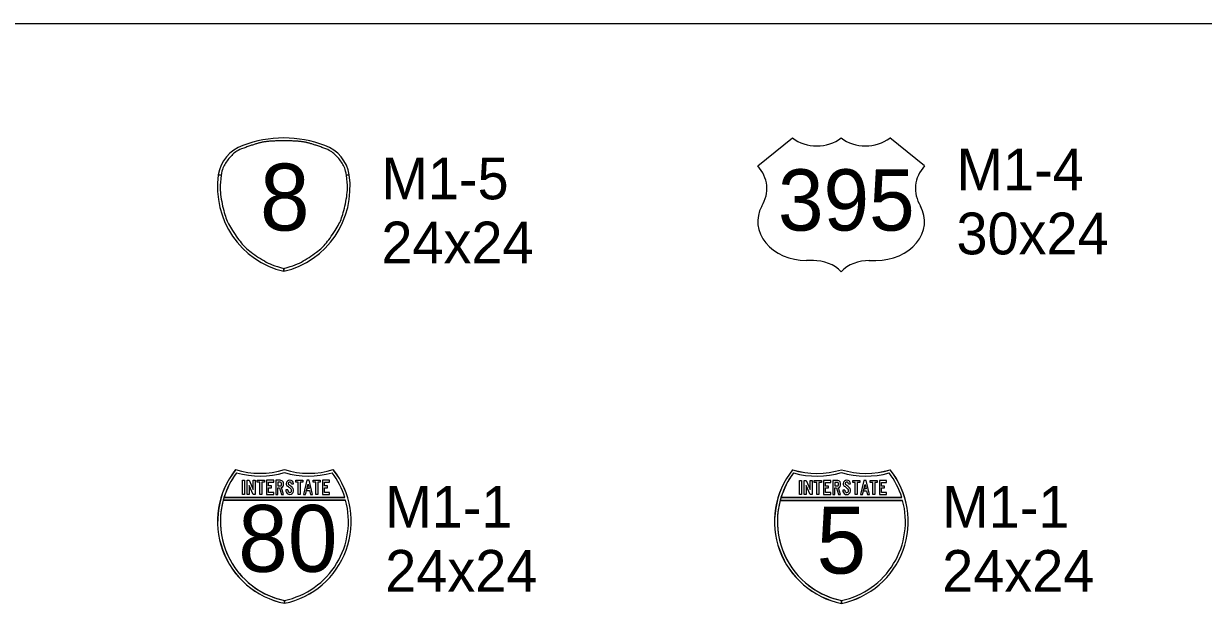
# Model space of a CAD drawing. Extents: x 1458 to 4498, y 17709 to 24109.
# Drawn here: x 1882 to 2305.5, y 20459 to 20667.1 of the extents above; entities that cross this region are included whole.
import ezdxf

# ---------------------------------------------------------------- set-up
doc = ezdxf.new("R2010")
doc.units = 0
doc.layers.add('P_ODOT_PLAN_TBlock', color=7, linetype='Continuous')
doc.layers.add('P_TRAF_TCP_General', color=7, linetype='Continuous')

msp = doc.modelspace()

# ---------------------------------------------------------------- linework, layer by layer
at = {"layer": 'P_ODOT_PLAN_TBlock'}
msp.add_line((1458.44, 20667.08), (3378.44, 20667.08), dxfattribs=at)
at = {"layer": 'P_TRAF_TCP_General'}
for p, q in [((2145.54, 20616.04), (2158.02, 20626.04)), ((2205.46, 20616.04), (2192.97, 20626.04)), ((1952.92, 20612.63), (1951.89, 20612.77)), ((1951.89, 20612.77), (1952.92, 20612.63)), ((1998.91, 20612.77), (1997.88, 20612.63)), ((1997.88, 20612.63), (1998.91, 20612.77)), ((2165.51, 20582.06), (2163.01, 20582.06)), ((2185.48, 20582.06), (2187.98, 20582.06)), ((1975.39, 20579.24), (1975.4, 20578.18)), ((1975.4, 20578.18), (1975.39, 20579.24)), ((1975.34, 20498.13), (1974.62, 20500.55)), ((1978.18, 20501.96), (1978.88, 20501.96)), ((2175.31, 20498.1), (2174.58, 20500.52)), ((2178.14, 20501.93), (2178.84, 20501.93)), ((1997.6, 20496.01), (1953.65, 20496.01)), ((1953.65, 20496.01), (1997.6, 20496.01)), ((1953.65, 20496.01), (1997.6, 20496.01)), ((1953.94, 20497.01), (1997.31, 20497.01)), ((1997.31, 20497.01), (1953.94, 20497.01)), ((1997.31, 20497.01), (1953.94, 20497.01)), ((1997.31, 20497.01), (1953.94, 20497.01)), ((1976.82, 20499.71), (1976.11, 20499.71)), ((1997.6, 20496.01), (1997.6, 20496.01)), ((2197.56, 20495.98), (2153.61, 20495.98)), ((2153.61, 20495.98), (2197.56, 20495.98)), ((2153.61, 20495.98), (2197.56, 20495.98)), ((2153.9, 20496.98), (2197.27, 20496.98)), ((2197.27, 20496.98), (2153.9, 20496.98)), ((2197.27, 20496.98), (2153.9, 20496.98)), ((2197.27, 20496.98), (2153.9, 20496.98)), ((2176.78, 20499.68), (2176.07, 20499.68)), ((2197.56, 20495.98), (2197.56, 20495.98)), ((1975.62, 20460.05), (1975.62, 20459.03)), ((1975.62, 20459.03), (1975.62, 20460.05)), ((1975.62, 20460.05), (1975.62, 20459.03)), ((1975.62, 20459.03), (1975.62, 20460.05)), ((1975.62, 20459.04), (1975.62, 20459.03)), ((1975.62, 20459.03), (1975.62, 20459.04)), ((2175.58, 20459), (2175.58, 20460.02)), ((2175.58, 20459), (2175.58, 20460.02)), ((2175.58, 20459), (2175.58, 20459.02)), ((2175.59, 20460.02), (2175.59, 20459)), ((2175.59, 20460.02), (2175.59, 20459)), ((2175.59, 20459.02), (2175.59, 20459))]:
    msp.add_line(p, q, dxfattribs=at)
for points in [[(1975.39, 20579.24), (1975.4, 20579.24), (1975.41, 20579.24)], [(1974.09, 20503.17), (1972.55, 20503.17), (1972.55, 20498.13), (1973.25, 20498.13), (1973.25, 20500.46), (1973.9, 20500.46), (1974.61, 20498.13), (1975.34, 20498.13)], [(1974.09, 20502.46), (1973.25, 20502.46), (1973.25, 20501.17), (1974.11, 20501.17)], [(2174.05, 20503.14), (2172.51, 20503.14), (2172.51, 20498.1), (2173.21, 20498.1), (2173.21, 20500.44), (2173.87, 20500.44), (2174.57, 20498.1), (2175.31, 20498.1)], [(2174.05, 20502.44), (2173.21, 20502.44), (2173.21, 20501.14), (2174.08, 20501.14)]]:
    msp.add_lwpolyline(points, dxfattribs=at)
for points in [[(1960.62, 20503.17), (1961.33, 20503.17), (1961.33, 20498.13), (1960.62, 20498.13)], [(1963, 20503.17), (1964.39, 20499.92), (1964.39, 20503.17), (1965.1, 20503.17), (1965.1, 20498.13), (1964.39, 20498.13), (1963.01, 20501.37), (1963.01, 20498.13), (1962.3, 20498.13), (1962.3, 20503.17)], [(1966.8, 20502.46), (1965.87, 20502.46), (1965.87, 20503.17), (1968.44, 20503.17), (1968.44, 20502.46), (1967.51, 20502.46), (1967.51, 20498.13), (1966.8, 20498.13)], [(1969.91, 20498.84), (1969.91, 20500.45), (1971.02, 20500.45), (1971.02, 20501.15), (1969.91, 20501.15), (1969.91, 20502.46), (1971.78, 20502.46), (1971.78, 20503.17), (1969.21, 20503.17), (1969.21, 20498.13), (1971.78, 20498.13), (1971.78, 20498.84)], [(1980.61, 20502.46), (1979.68, 20502.46), (1979.68, 20503.17), (1982.25, 20503.17), (1982.25, 20502.46), (1981.32, 20502.46), (1981.32, 20498.13), (1980.61, 20498.13)], [(1983.72, 20500.19), (1983.55, 20499.48), (1984.65, 20499.48), (1984.97, 20498.13), (1985.7, 20498.13), (1984.48, 20503.17), (1983.72, 20503.17), (1982.5, 20498.13), (1983.23, 20498.13), (1984.1, 20501.73), (1984.48, 20500.19)], [(1986.88, 20502.46), (1985.95, 20502.46), (1985.95, 20503.17), (1988.52, 20503.17), (1988.52, 20502.46), (1987.59, 20502.46), (1987.59, 20498.13), (1986.88, 20498.13)], [(1989.99, 20498.84), (1989.99, 20500.45), (1991.1, 20500.45), (1991.1, 20501.15), (1989.99, 20501.15), (1989.99, 20502.46), (1991.86, 20502.46), (1991.86, 20503.17), (1989.29, 20503.17), (1989.29, 20498.13), (1991.86, 20498.13), (1991.86, 20498.84)], [(2160.58, 20503.14), (2161.29, 20503.14), (2161.29, 20498.1), (2160.58, 20498.1)], [(2162.96, 20503.14), (2164.35, 20499.9), (2164.35, 20503.14), (2165.06, 20503.14), (2165.06, 20498.1), (2164.35, 20498.1), (2162.97, 20501.34), (2162.97, 20498.1), (2162.26, 20498.1), (2162.26, 20503.14)], [(2166.76, 20502.44), (2165.83, 20502.44), (2165.83, 20503.14), (2168.4, 20503.14), (2168.4, 20502.44), (2167.47, 20502.44), (2167.47, 20498.1), (2166.76, 20498.1)], [(2169.87, 20498.81), (2169.87, 20500.42), (2170.98, 20500.42), (2170.98, 20501.13), (2169.87, 20501.13), (2169.87, 20502.44), (2171.74, 20502.44), (2171.74, 20503.14), (2169.17, 20503.14), (2169.17, 20498.1), (2171.74, 20498.1), (2171.74, 20498.81)], [(2180.58, 20502.44), (2179.64, 20502.44), (2179.64, 20503.14), (2182.21, 20503.14), (2182.21, 20502.44), (2181.28, 20502.44), (2181.28, 20498.1), (2180.58, 20498.1)], [(2183.69, 20500.16), (2183.51, 20499.45), (2184.61, 20499.45), (2184.93, 20498.1), (2185.66, 20498.1), (2184.44, 20503.14), (2183.68, 20503.14), (2182.46, 20498.1), (2183.19, 20498.1), (2184.06, 20501.71), (2184.44, 20500.16)], [(2186.84, 20502.44), (2185.91, 20502.44), (2185.91, 20503.14), (2188.48, 20503.14), (2188.48, 20502.44), (2187.55, 20502.44), (2187.55, 20498.1), (2186.84, 20498.1)], [(2189.96, 20498.81), (2189.96, 20500.42), (2191.06, 20500.42), (2191.06, 20501.13), (2189.96, 20501.13), (2189.96, 20502.44), (2191.82, 20502.44), (2191.82, 20503.14), (2189.25, 20503.14), (2189.25, 20498.1), (2191.82, 20498.1), (2191.82, 20498.81)]]:
    msp.add_lwpolyline(points, close=True, dxfattribs=at)
for centre, radius, start, end in [((1981.62, 20488.41), 29.99, 141.6689, 258.4631), ((1981.62, 20488.41), 29.99, 141.6689, 258.4631), ((1981.62, 20488.41), 29.99, 141.6689, 258.4631), ((1981.62, 20488.41), 29.99, 141.6689, 258.4631), ((1981.62, 20488.41), 29.97, 141.6894, 258.4569), ((1981.62, 20488.41), 28.99, 142.9958, 258.0595), ((1981.62, 20488.41), 28.99, 142.9958, 258.0595), ((1981.62, 20488.41), 28.99, 142.9957, 162.7366), ((1981.62, 20488.41), 28.99, 142.9958, 162.7366), ((1966.86, 20535.69), 29.99, 253.0091, 286.9909), ((1966.86, 20535.69), 29.99, 253.0091, 286.9909), ((1966.86, 20535.69), 29.99, 253.0091, 286.9909), ((1966.86, 20535.69), 29.99, 253.0091, 286.9909), ((1966.86, 20535.69), 30, 253.0296, 286.9817), ((1966.86, 20535.69), 30.99, 254.2925, 286.427), ((1966.86, 20535.69), 30.99, 254.2925, 286.427), ((1966.86, 20535.69), 30.99, 254.2925, 286.427), ((1966.86, 20535.69), 30.99, 254.2925, 286.427), ((1984.39, 20535.69), 29.99, 253.0091, 286.9909), ((1969.63, 20488.41), 29.99, 281.5369, 38.3311), ((1969.63, 20488.41), 29.99, 281.5385, 38.3311), ((1984.39, 20535.69), 29.99, 253.0091, 286.9909), ((1969.63, 20488.41), 29.99, 281.5385, 38.3311), ((1984.39, 20535.69), 29.99, 253.0091, 286.9909), ((1969.63, 20488.41), 29.99, 281.5385, 38.3311), ((1984.39, 20535.69), 29.99, 253.0091, 286.9909), ((1984.39, 20535.69), 30, 253.0183, 286.9704), ((1969.63, 20488.41), 29.97, 281.5446, 38.3106), ((1984.39, 20535.69), 30.99, 253.573, 285.7075), ((1984.39, 20535.69), 30.99, 253.573, 285.7075), ((1984.39, 20535.69), 30.99, 253.573, 285.7075), ((1984.39, 20535.69), 30.99, 253.573, 285.7075), ((1969.63, 20488.41), 28.99, 17.2633, 37.0042), ((1969.63, 20488.41), 28.99, 17.2633, 37.0042), ((1969.63, 20488.41), 28.99, 17.2633, 37.0042), ((1969.63, 20488.41), 28.99, 17.2633, 37.0042), ((2181.58, 20488.38), 29.99, 141.6689, 258.4631), ((2181.58, 20488.38), 29.99, 141.6689, 258.4631), ((2181.58, 20488.38), 29.99, 141.6689, 258.4631), ((2181.58, 20488.38), 29.99, 141.6689, 258.4631), ((2181.58, 20488.38), 29.97, 141.6894, 258.4569), ((2181.58, 20488.38), 28.99, 142.9958, 258.0595), ((2181.58, 20488.38), 28.99, 142.9958, 258.0595), ((2181.58, 20488.38), 28.99, 142.9957, 162.7366), ((2181.58, 20488.38), 28.99, 142.9958, 162.7366), ((2166.82, 20535.66), 29.99, 253.0091, 286.9909), ((2166.82, 20535.66), 29.99, 253.0091, 286.9909), ((2166.82, 20535.66), 29.99, 253.0091, 286.9909), ((2166.82, 20535.66), 29.99, 253.0091, 286.9909), ((2166.82, 20535.66), 30, 253.0296, 286.9817), ((2166.82, 20535.66), 30.99, 254.2925, 286.427), ((2166.82, 20535.66), 30.99, 254.2925, 286.427), ((2166.82, 20535.66), 30.99, 254.2925, 286.427), ((2166.82, 20535.66), 30.99, 254.2925, 286.427), ((2184.35, 20535.66), 29.99, 253.0091, 286.9909), ((2169.59, 20488.38), 29.99, 281.5369, 38.3311), ((2184.35, 20535.66), 29.99, 253.0091, 286.9909), ((2184.35, 20535.66), 29.99, 253.0091, 286.9909), ((2184.35, 20535.66), 29.99, 253.0091, 286.9909), ((2184.35, 20535.66), 30, 253.0183, 286.9704), ((2184.35, 20535.66), 30.99, 253.573, 285.7075), ((2184.35, 20535.66), 30.99, 253.573, 285.7075), ((2184.35, 20535.66), 30.99, 253.573, 285.7075), ((2184.35, 20535.66), 30.99, 253.573, 285.7075), ((2169.59, 20488.38), 29.99, 281.5385, 38.3311), ((2169.59, 20488.38), 29.99, 281.5385, 38.3311), ((2169.59, 20488.38), 29.99, 281.5385, 38.3311), ((2169.59, 20488.38), 29.97, 281.5446, 38.3106), ((2169.59, 20488.38), 28.99, 17.2633, 37.0042), ((2169.59, 20488.38), 28.99, 17.2633, 37.0042), ((2169.59, 20488.38), 28.99, 17.2633, 37.0042), ((2169.59, 20488.38), 28.99, 17.2633, 37.0042), ((1974.11, 20501.96), 1.21, 32.7773, 91.1677), ((1974.11, 20501.95), 0.519, 26.159, 91.9542), ((1974.15, 20501.62), 0.455, 265.1381, 343.1073), ((1973.33, 20501.8), 1.3, 346.1097, 16.6195), ((1974.12, 20501.64), 1.2, 294.5283, 328.7975), ((1973.66, 20501.81), 1.68, 332.0334, 28.7465), ((1977.58, 20501.93), 1.31, 1.3681, 176.3683), ((1977.44, 20501.97), 1.17, 177.9393, 233.9136), ((1974.32, 20496.53), 5.1, 45.9941, 61.57), ((1977.49, 20501.99), 0.507, 140.0639, 242.2325), ((1977.57, 20501.91), 0.615, 4.2694, 139.1342), ((1974.94, 20497.3), 4.83, 43.0003, 61.2981), ((1977.34, 20499.51), 0.872, 333.7597, 52.7126), ((1977.35, 20499.51), 1.56, 334.1366, 44.3106), ((2174.07, 20501.93), 1.21, 32.7773, 91.1677), ((2174.07, 20501.92), 0.519, 26.159, 91.9542), ((2174.11, 20501.59), 0.455, 265.1381, 343.1073), ((2173.29, 20501.77), 1.3, 346.1097, 16.6195), ((2174.08, 20501.61), 1.2, 294.5283, 328.7975), ((2173.62, 20501.78), 1.68, 332.0334, 28.7465), ((2177.54, 20501.9), 1.31, 1.3681, 176.3683), ((2177.41, 20501.94), 1.17, 177.9393, 233.9136), ((2174.28, 20496.5), 5.1, 45.9941, 61.57), ((2177.45, 20501.96), 0.507, 140.0639, 242.2325), ((2177.53, 20501.88), 0.615, 4.2694, 139.1342), ((2174.9, 20497.27), 4.83, 43.0003, 61.2981), ((2177.3, 20499.48), 0.872, 333.7597, 52.7126), ((2177.31, 20499.48), 1.56, 334.1366, 44.3106), ((1981.62, 20488.41), 28.99, 164.7945, 258.0595), ((1981.62, 20488.41), 28.99, 162.7361, 164.7941), ((1981.62, 20488.41), 28.99, 162.7361, 164.7941), ((1969.63, 20488.41), 28.99, 281.9405, 15.2055), ((1969.63, 20488.41), 28.99, 281.9421, 15.2055), ((1969.63, 20488.41), 28.99, 281.9421, 15.2055), ((1977.75, 20499.64), 1.65, 177.4542, 244.795), ((1977.82, 20499.67), 1, 177.3621, 220.757), ((1977.53, 20499.43), 1.37, 249.6288, 333.604), ((1977.56, 20499.42), 0.639, 219.5909, 332.3646), ((2181.58, 20488.38), 28.99, 164.7945, 258.0595), ((2181.58, 20488.38), 28.99, 162.7361, 164.7941), ((2181.58, 20488.38), 28.99, 162.7361, 164.7941), ((2169.59, 20488.38), 28.99, 281.9405, 15.2055), ((2169.59, 20488.38), 28.99, 281.9421, 15.2055), ((2169.59, 20488.38), 28.99, 281.9421, 15.2055), ((2177.72, 20499.61), 1.65, 177.4542, 244.795), ((2177.78, 20499.64), 1, 177.3621, 220.757), ((2177.49, 20499.41), 1.37, 249.6288, 333.604), ((2177.52, 20499.39), 0.639, 219.5909, 332.3646)]:
    msp.add_arc(centre, radius, start, end, dxfattribs=at)
for centre, major_axis, ratio, start_param, end_param in [((1965.01, 20610.64), (0, -13.47), 0.986381, 3.475854, 4.553452), ((1975.4, 20582.92), (0, 43.11), 0.986381, 0.000035, 0.354204), ((1975.4, 20582.92), (0, 43.11), 0.986381, 5.928982, 6.283151), ((1985.79, 20610.64), (0, -13.47), 0.986381, 1.729734, 2.807332), ((2166.75, 20633.19), (12.5, 0), 0.800797, 3.938089, 5.486644), ((2184.23, 20633.2), (12.5, 0), 0.800797, 3.938168, 5.483887), ((2131.36, 20607.86), (17.48, 0), 0.800797, 5.818099, 6.907814), ((2219.63, 20607.86), (-17.48, 0), 0.800797, 5.658557, 6.748272), ((1982.26, 20608.47), (0, -31.08), 0.986381, 4.573624, 6.057627), ((1968.55, 20608.47), (0, -31.08), 0.986381, 0.225558, 1.709562), ((2163.03, 20596.05), (17.48, 0), 0.800797, 2.735208, 4.711234), ((2187.96, 20596.05), (-17.48, 0), 0.800797, 1.571951, 3.547977), ((2165.52, 20572.05), (12.48, 0), 0.800797, 0.644236, 1.590116), ((2185.48, 20572.05), (-12.48, 0), 0.800797, 4.693069, 5.638949)]:
    msp.add_ellipse(centre, major_axis=major_axis, ratio=ratio, start_param=start_param, end_param=end_param, dxfattribs=at)
for points, degree in [([(1975.4, 20625), (1970.49, 20625), (1965.62, 20624.12), (1961.02, 20622.39)], 2), ([(1989.79, 20622.39), (1985.18, 20624.12), (1980.31, 20625), (1975.4, 20625)], 2), ([(1961, 20622.39), (1958.92, 20621.65), (1957.05, 20620.35), (1954.21, 20616.92), (1953.27, 20614.82), (1952.92, 20612.61)], 3), ([(1997.89, 20612.61), (1997.54, 20614.82), (1996.59, 20616.92), (1993.76, 20620.35), (1991.89, 20621.65), (1989.81, 20622.39)], 3), ([(1952.92, 20612.63), (1952.41, 20608.93), (1952.59, 20605.18), (1954.27, 20597.94), (1955.79, 20594.47), (1959.94, 20588.37), (1962.6, 20585.69), (1968.59, 20581.57), (1971.9, 20580.09), (1975.39, 20579.24)], 3), ([(1975.41, 20579.24), (1978.91, 20580.09), (1982.22, 20581.57), (1988.21, 20585.69), (1990.86, 20588.37), (1995.01, 20594.47), (1996.53, 20597.94), (1998.22, 20605.18), (1998.39, 20608.93), (1997.88, 20612.63)], 3)]:
    msp.add_open_spline(points, degree=degree, dxfattribs=at)

# ---------------------------------------------------------------- texts
for s, height, p in [('M1-5', 14.994, (2010.44, 20604.01)), ('M1-4', 14.994, (2216.9, 20607.25)), ('8', 23.99, (1966.83, 20592.82)), ('395', 21.991, (2152.81, 20592.79)), ('30x24', 14.994, (2216.9, 20584.26)), ('24x24', 14.994, (2010.44, 20581.02)), ('M1-1', 14.994, (2011.82, 20486.17)), ('M1-1', 14.994, (2211.78, 20486.14)), ('80', 23.99, (1959.01, 20470.33)), ('5', 23.99, (2166.66, 20469.71)), ('24x24', 14.994, (2011.82, 20463.18)), ('24x24', 14.994, (2211.78, 20463.15))]:
    msp.add_text(s, height=height, dxfattribs=at).set_placement(p)

doc.saveas('drawing.dxf')
